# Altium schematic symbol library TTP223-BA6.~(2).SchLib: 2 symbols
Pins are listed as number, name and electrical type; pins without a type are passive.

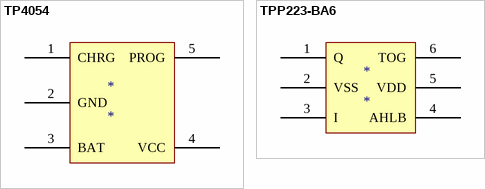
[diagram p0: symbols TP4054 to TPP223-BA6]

## TP4054
designator *
pins: 1 CHRG, 2 GND, 3 BAT, 4 VCC, 5 PROG

## TPP223-BA6
designator *
pins: 1 Q, 2 VSS, 3 I, 4 AHLB, 5 VDD, 6 TOG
